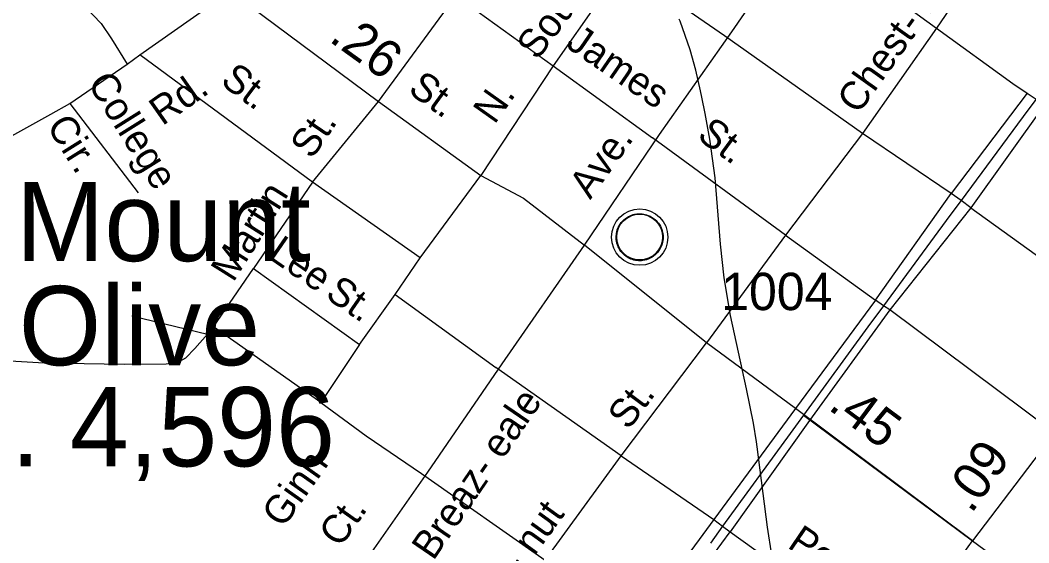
# Model space of a CAD drawing. Extents: x 2206922 to 2357709, y 510027 to 673830.
# Drawn here: x 2276050 to 2279424, y 526951 to 528698 of the extents above; entities that cross this region are included whole.
import ezdxf

# ---------------------------------------------------------------- set-up
doc = ezdxf.new("R2010")
doc.units = 0
for name, color, linetype in [('Exist Civil Demographics City Label', 7, 'Continuous'), ('Exist Civil Demographics Community CELL', 7, 'Continuous'), ('Exist Hydrographic Misc Water Feature', 7, 'Continuous'), ('Exist Railroad Mainline', 7, 'Continuous'), ('Exist Road Non-System Type 51', 7, 'Continuous'), ('Exist Road Non-System Type 51 Label', 7, 'Continuous'), ('Exist Road Primary US Attributed', 7, 'Continuous'), ('Exist Road Primary US Label', 7, 'Continuous'), ('Exist Road Secondary Mileage Hundredths English Label', 7, 'Continuous'), ('Exist Road Secondary Type 51 Attributed', 7, 'Continuous'), ('Exist Road Secondary Type 51 Label', 7, 'Continuous'), ('Exist Road Secondary Type 51 Number Label', 7, 'Continuous')]:
    doc.layers.add(name, color=color, linetype=linetype)

msp = doc.modelspace()

# ---------------------------------------------------------------- linework, layer by layer
at = {"layer": 'Exist Civil Demographics Community CELL'}
msp.add_lwpolyline([(2278044.5, 527985.3), (2278045.5, 527990.9), (2278047.3, 527997.5), (2278050.2, 528004.7), (2278053.1, 528010.4), (2278056.5, 528016.2), (2278060.2, 528021.3), (2278064.2, 528025.7), (2278068.8, 528030.3), (2278074.3, 528034.9), (2278079.7, 528038.5), (2278084.6, 528041.4), (2278089.7, 528043.8), (2278095.1, 528046.1), (2278100.8, 528048), (2278105.1, 528049.1), (2278109.9, 528049.8), (2278114.1, 528050.6), (2278120.4, 528050.8), (2278124.9, 528050.7), (2278130.5, 528050.5), (2278135.4, 528049.7), (2278140.3, 528048.7), (2278145.3, 528047.3), (2278150.5, 528045.4), (2278157.2, 528042.5), (2278163.4, 528039), (2278168.5, 528035.4), (2278173.7, 528031.4), (2278177, 528028.3), (2278181.1, 528023.9), (2278185, 528019.2), (2278188, 528014.6), (2278191.2, 528009.6), (2278193.6, 528004.4), (2278195.7, 527999.4), (2278197.2, 527994.4), (2278198.5, 527989.8), (2278199.6, 527983.8), (2278200.2, 527979.1), (2278200.5, 527973.1), (2278200.3, 527967.3), (2278199.7, 527961.6), (2278198.8, 527956.1), (2278197.1, 527950), (2278195.3, 527944.1), (2278193, 527939.1), (2278189.8, 527933.1), (2278186.5, 527927.7), (2278183.1, 527923), (2278178.8, 527918.3), (2278173.6, 527913.3), (2278168.5, 527909.2), (2278163.5, 527905.8), (2278159.2, 527903.3), (2278152.4, 527900), (2278145.2, 527897.3), (2278139.3, 527895.9), (2278132.7, 527894.5), (2278128.3, 527894.1), (2278123.8, 527893.8), (2278118.2, 527893.8), (2278113.9, 527894.2), (2278108.3, 527895), (2278102.4, 527896.3), (2278097.8, 527897.6), (2278092.6, 527899.5), (2278088, 527901.4), (2278084.1, 527903.7), (2278077.3, 527907.7), (2278071.7, 527912), (2278066.8, 527916.5), (2278062.3, 527921.4), (2278059.2, 527925.3), (2278056.2, 527929.5), (2278052.1, 527936.6), (2278050.4, 527940.2), (2278048.6, 527944.2), (2278046.1, 527952.4), (2278044.5, 527959.4), (2278043.8, 527964.6), (2278043.5, 527970.9), (2278043.4, 527975.6), (2278044, 527982.1)], close=True, dxfattribs=at)
for centre, radius in [((2278122.1, 527972.9), 94.3), ((2278121.9, 527973.2), 76.7)]:
    msp.add_circle(centre, radius, dxfattribs=at)
at = {"layer": 'Exist Hydrographic Misc Water Feature'}
for p, q in [((2278257, 528694.4), (2278253.9, 528702)), ((2278405.1, 527836.7), (2278391.9, 527949.5)), ((2278515, 527271.6), (2278512.3, 527288.3))]:
    msp.add_line(p, q, dxfattribs=at)
for points in [[(2278330.2, 528440.7), (2278325.9, 528462), (2278309.9, 528531.3), (2278290.8, 528598.5), (2278257, 528694.4)], [(2278330.2, 528440.7), (2278325.9, 528462), (2278309.9, 528531.3), (2278290.8, 528598.5), (2278257, 528694.4)], [(2278356.9, 528300.6), (2278341.1, 528386.6), (2278330.2, 528440.7)], [(2278356.9, 528300.6), (2278341.1, 528386.6), (2278330.2, 528440.7)], [(2278391.9, 527949.5), (2278374.9, 528170.8), (2278356.9, 528300.6)], [(2278391.9, 527949.5), (2278374.9, 528170.8), (2278356.9, 528300.6)], [(2278512.3, 527288.3), (2278502.3, 527350.6), (2278478.9, 527466.2), (2278426.2, 527710.8), (2278405.1, 527836.7)], [(2278512.3, 527288.3), (2278502.3, 527350.6), (2278478.9, 527466.2), (2278426.2, 527710.8), (2278405.1, 527836.7)], [(2278563.6, 526909.4), (2278550, 527002.9), (2278515, 527271.6)], [(2278563.6, 526909.4), (2278550, 527002.9), (2278515, 527271.6)]]:
    msp.add_lwpolyline(points, dxfattribs=at)
at = {"layer": 'Exist Railroad Mainline'}
for points in [[(2279590.3, 528620.7), (2279448.4, 528434), (2279420.4, 528397.2), (2279196.7, 528094.8), (2279159.8, 528045), (2278937.9, 527743.7), (2278885.6, 527672.7), (2278669.6, 527377.5)], [(2278669.6, 527377.5), (2278625, 527316.5), (2278399.6, 527006.4), (2278358.7, 526950.2)]]:
    msp.add_lwpolyline(points, dxfattribs=at)
at = {"layer": 'Exist Road Non-System Type 51'}
for p, q in [((2279367.1, 529044.8), (2279115.1, 528671.8)), ((2278655.4, 529004.2), (2279115.1, 528671.8)), ((2278066.4, 528880.9), (2277832.3, 528545.2)), ((2278406.2, 528645.4), (2278066.4, 528880.9)), ((2277248.9, 528426.4), (2277507.4, 528779.3)), ((2277554, 528746.7), (2277832.3, 528545.2)), ((2279115.1, 528671.8), (2278867.3, 528319.2)), ((2279115.1, 528671.8), (2279369.7, 528486.6)), ((2278867.3, 528319.2), (2278406.2, 528645.4)), ((2277027.7, 528156.1), (2276450.3, 528582.5)), ((2277832.3, 528545.2), (2277591.2, 528179.4)), ((2277832.3, 528545.2), (2278165.2, 528305.2)), ((2279369.7, 528486.6), (2279417.8, 528454.3)), ((2279417.8, 528454.3), (2279164.2, 528118.8)), ((2279417.8, 528454.3), (2279448.4, 528434)), ((2276216.2, 528419.4), (2276444.6, 528121.5)), ((2277027.7, 528156.1), (2277248.9, 528426.4)), ((2279476.3, 528415.6), (2279229.2, 528070.9)), ((2278610, 527979), (2278165.2, 528305.2)), ((2278867.3, 528319.2), (2278610, 527979)), ((2279164.2, 528118.8), (2278867.3, 528319.2)), ((2277387.5, 527903.3), (2277591.2, 528179.4)), ((2277027.7, 528156.1), (2276830.1, 527867.9)), ((2277387.5, 527903.3), (2277027.7, 528156.1)), ((2278910.6, 527762.4), (2279164.2, 528118.8)), ((2279196.7, 528094.8), (2279164.2, 528118.8)), ((2279229.2, 528070.9), (2279196.7, 528094.8)), ((2279229.2, 528070.9), (2278958.8, 527729.3)), ((2279229.2, 528070.9), (2279774.5, 527678.3)), ((2278610, 527979), (2278345.5, 527619.5)), ((2278610, 527979), (2278910.6, 527762.4)), ((2277304.3, 527781.3), (2277387.5, 527903.3)), ((2276697.2, 527673.1), (2276830.1, 527867.9)), ((2276830.1, 527867.9), (2277185.4, 527614.4)), ((2277185.4, 527614.4), (2277304.3, 527781.3)), ((2277304.3, 527781.3), (2277641.1, 527537.1)), ((2278910.6, 527762.4), (2278643.7, 527400)), ((2278937.9, 527743.7), (2278910.6, 527762.4)), ((2278958.8, 527729.3), (2278690, 527359.8)), ((2278958.8, 527729.3), (2278937.9, 527743.7)), ((2279508.8, 527318.1), (2278958.8, 527729.3)), ((2276423.8, 527710.2), (2276677.1, 527648.4)), ((2276697.2, 527673.1), (2276677.1, 527648.4)), ((2277055.6, 527419.6), (2276697.2, 527673.1)), ((2277185.4, 527614.4), (2277055.6, 527419.6)), ((2278059.8, 527241.9), (2278345.5, 527619.5)), ((2278059.8, 527241.9), (2277641.1, 527537.1)), ((2278643.7, 527400), (2278370.2, 527029.1)), ((2278690, 527359.8), (2278424.3, 526987.3)), ((2277806.4, 526892.5), (2278059.8, 527241.9)), ((2278059.8, 527241.9), (2278370.2, 527029.1)), ((2277392.4, 527183.1), (2277806.4, 526892.5)), ((2278370.2, 527029.1), (2278166.5, 526751.5)), ((2278370.2, 527029.1), (2278399.6, 527006.4)), ((2278166.3, 526638), (2278424.3, 526987.3)), ((2278399.6, 527006.4), (2278424.3, 526987.3)), ((2278424.3, 526987.3), (2278974.3, 526596.3)), ((2279235.3, 526958), (2279704.9, 526613.4))]:
    msp.add_line(p, q, dxfattribs=at)
for points in [[(2275578.2, 529244.2), (2275600.3, 529229), (2275632.9, 529206.9), (2275910, 529004.2), (2276032.3, 528911), (2276109.1, 528856.2), (2276175.5, 528806.1), (2276210.4, 528784), (2276261.6, 528745.6), (2276294.2, 528715.3), (2276321, 528687.3), (2276355.9, 528636.1), (2276408.3, 528551)], [(2275343.7, 527841.3), (2275404.2, 527838.5), (2275432, 527833.9), (2275473.7, 527820), (2275554, 527785.9), (2275773.4, 527657.7), (2275876.9, 527597.4), (2275923.3, 527574.2), (2275997.4, 527560.3), (2276130.3, 527552.5), (2276397.5, 527547.9), (2276538.1, 527549.5), (2276581.4, 527557.2), (2276604.5, 527569.5), (2276633.9, 527600.5), (2276677.1, 527648.4)], [(2277055.6, 527419.6), (2277207, 527308.3), (2277392.4, 527183.1)]]:
    msp.add_lwpolyline(points, dxfattribs=at)
at = {"layer": 'Exist Road Primary US Attributed'}
for points in [[(2277938, 527945.9), (2278188, 528315.7), (2278430.1, 528659.6), (2278684, 529027.8), (2278932.4, 529385.1), (2278933.4, 529386.4)], [(2275505.2, 523730.3), (2275769.4, 524243.4), (2275826.9, 524351.4), (2275997.3, 524691.3), (2276061.9, 524817.5), (2276106.9, 524902.7), (2276141.6, 524976), (2276320.6, 525315.9), (2276558, 525782.7), (2276633.7, 525933.4), (2276708.6, 526084), (2276774, 526207.8), (2276852.1, 526354.5), (2276879.7, 526407.3), (2276900.2, 526436.5), (2276993.3, 526577.7), (2277078.4, 526703.8), (2277156.5, 526819), (2277413.6, 527186.5), (2277662, 527549.2), (2277938, 527945.9)]]:
    msp.add_lwpolyline(points, dxfattribs=at)
at = {"layer": 'Exist Road Secondary Type 51 Attributed'}
msp.add_line((2279508.8, 527318.1), (2279235.3, 526958), dxfattribs=at)
for points in [[(2276754.1, 528793.3), (2276818.2, 528746.7), (2277248.9, 528426.4), (2277591.2, 528179.4), (2277733.8, 528103.6), (2277938, 527945.9)], [(2275981.3, 528288.9), (2276152.2, 528384.4), (2276216.2, 528419.4), (2276408.3, 528551), (2276450.3, 528582.5), (2276682.6, 528745.4)], [(2278669.6, 527377.5), (2279235.3, 526958), (2278643.7, 527400), (2278345.5, 527619.5), (2277938, 527945.9)], [(2278449, 525885.3), (2278720.9, 526248.5), (2278974.3, 526596.3), (2279235.3, 526958)]]:
    msp.add_lwpolyline(points, dxfattribs=at)

# ---------------------------------------------------------------- texts
at = {"layer": 'Exist Civil Demographics City Label'}
for s, p in [('Mount', (2276036.7, 527892.6)), ('Olive', (2276045.6, 527544.5)), ('Pop. 4,596', (2275388.7, 527206.3))]:
    msp.add_text(s, height=265, dxfattribs=at).set_placement(p)
at = {"layer": 'Exist Road Non-System Type 51 Label'}
for s, rotation, p in [('South- land', 53.2719, (2277779.7, 528561.2)), ('James', 325.4343, (2277871.1, 528610.8)), ('St.', 323.0307, (2276716, 528486.9)), ('College', 302.0514, (2276273.4, 528487.8)), ('N.', 54.6939, (2277636.5, 528346.9)), ('Cir.', 302.0514, (2276136.4, 528345.1)), ('St.', 55.671, (2277025.8, 528230.2)), ('St.', 323.7489, (2278310, 528304.1)), ('Martin', 57.8846, (2276762.8, 527818.9)), ('Lee', 325.3317, (2276874.5, 527905.5)), ('St.', 325.3317, (2277066.5, 527772.7)), ('St.', 53.3059, (2278084.7, 527324.7)), ('Ginn', 54.7501, (2276929.7, 526996.9)), ('Chest- nut', 54.0617, (2277529.5, 526572.7)), ('Ct.', 54.7501, (2277120.5, 526931.7)), ('Pollock', 325.821, (2278612.5, 526936.9))]:
    msp.add_text(s, height=95, rotation=rotation, dxfattribs=at).set_placement(p)
at = {"layer": 'Exist Road Primary US Label'}
for s, rotation, p in [('Ave.', 54.4328, (2277956.7, 528095.9)), ('Breaz- eale', 55.6161, (2277431.8, 526888.2))]:
    msp.add_text(s, height=95, rotation=rotation, dxfattribs=at).set_placement(p)
at = {"layer": 'Exist Road Secondary Mileage Hundredths English Label'}
for s, rotation, p in [('.26', 324.2788, (2277079.5, 528630.1)), ('.45', 323.2348, (2278748.8, 527399.5)), ('.09', 54.5737, (2279231.2, 527045.4))]:
    msp.add_text(s, height=125, rotation=rotation, dxfattribs=at).set_placement(p)
at = {"layer": 'Exist Road Secondary Type 51 Label'}
for s, rotation, p in [('Chest- nut', 54.5042, (2278853.1, 528380.2)), ('Rd.', 35.0767, (2276525.6, 528343.1)), ('St.', 324.0308, (2277343.3, 528458.3))]:
    msp.add_text(s, height=95, rotation=rotation, dxfattribs=at).set_placement(p)
at = {"layer": 'Exist Road Secondary Type 51 Number Label'}
msp.add_text('1004', height=125, dxfattribs=at).set_placement((2278394.8, 527728.7))

doc.saveas('drawing.dxf')
